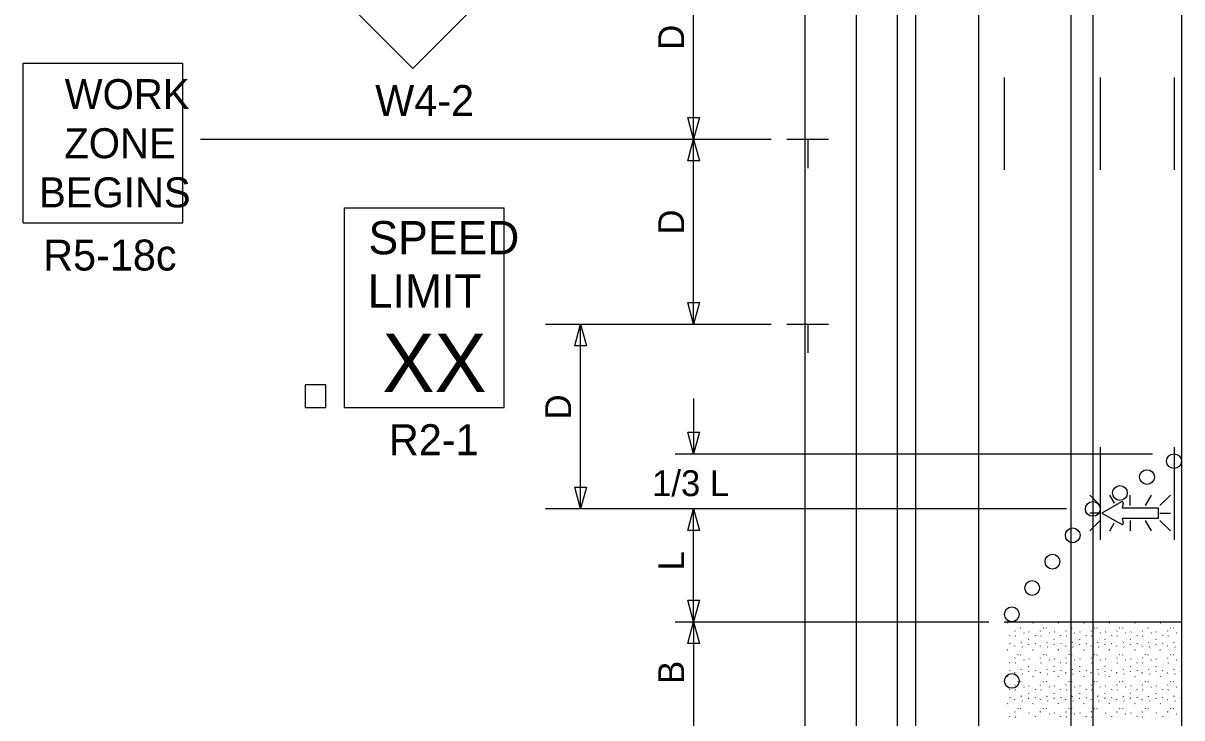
# Model space of a CAD drawing. Extents: x 16735 to 18475, y 6983 to 8262.
# Drawn here: x 16751.7 to 17065.2, y 7864.5 to 8052.4 of the extents above; entities that cross this region are included whole.
import ezdxf

# ---------------------------------------------------------------- set-up
doc = ezdxf.new("R2010")
doc.units = 0
for name, color, linetype in [('ALI_LEGAL_EX', 7, 'Continuous'), ('MT_SCRATCH_LEVEL_A', 7, 'Continuous'), ('PAVT_EDGE_EX', 7, 'Continuous'), ('TRAFFIC_SIGNS_PR', 7, 'Continuous'), ('TYPICAL_TEXT_DIMEN_PR', 7, 'Continuous')]:
    doc.layers.add(name, color=color, linetype=linetype)

msp = doc.modelspace()

# ---------------------------------------------------------------- linework, layer by layer
at = {"layer": 'ALI_LEGAL_EX'}
for points in [[(17017.08, 8037.7), (17017.08, 8012.7)], [(17043.08, 8037.7), (17043.08, 8012.7)], [(17063.08, 8037.7), (17063.08, 8012.7)], [(17043.08, 7937.7), (17043.08, 7912.7)], [(17063.08, 7937.7), (17063.08, 7912.7)]]:
    msp.add_lwpolyline(points, dxfattribs=at)
at = {"layer": 'MT_SCRATCH_LEVEL_A'}
for p, q in [((17017.08, 7890.49), (17065.16, 7890.49)), ((17018.01, 7890.13), (17018.06, 7890.25)), ((17024.9, 7890.13), (17024.95, 7890.25)), ((17031.78, 7890.13), (17031.83, 7890.25)), ((17038.67, 7890.13), (17038.72, 7890.25)), ((17045.56, 7890.13), (17045.61, 7890.25)), ((17052.45, 7890.13), (17052.5, 7890.25)), ((17059.33, 7890.13), (17059.39, 7890.25)), ((17018.58, 7886.81), (17018.63, 7886.73)), ((17020.03, 7887.93), (17020.08, 7888.05)), ((17020.11, 7886.67), (17020.16, 7886.59)), ((17020.79, 7888.89), (17020.84, 7888.82)), ((17021.53, 7888.87), (17021.58, 7888.79)), ((17022.4, 7887.49), (17022.45, 7887.41)), ((17023.85, 7887.64), (17023.9, 7887.75)), ((17025.47, 7886.81), (17025.52, 7886.73)), ((17026.92, 7887.93), (17026.97, 7888.05)), ((17027, 7886.67), (17027.05, 7886.59)), ((17027.68, 7888.89), (17027.73, 7888.82)), ((17028.42, 7888.87), (17028.47, 7888.79)), ((17029.28, 7887.49), (17029.34, 7887.41)), ((17030.74, 7887.64), (17030.79, 7887.75)), ((17032.35, 7886.81), (17032.4, 7886.73)), ((17033.8, 7887.93), (17033.85, 7888.05)), ((17033.88, 7886.67), (17033.94, 7886.59)), ((17034.57, 7888.89), (17034.62, 7888.82)), ((17035.3, 7888.87), (17035.36, 7888.79)), ((17036.17, 7887.49), (17036.22, 7887.41)), ((17037.62, 7887.64), (17037.67, 7887.75)), ((17039.24, 7886.81), (17039.29, 7886.73)), ((17040.69, 7887.93), (17040.74, 7888.05)), ((17040.77, 7886.67), (17040.82, 7886.59)), ((17041.46, 7888.89), (17041.51, 7888.82)), ((17042.19, 7888.87), (17042.24, 7888.79)), ((17043.06, 7887.49), (17043.11, 7887.41)), ((17044.51, 7887.64), (17044.56, 7887.75)), ((17046.13, 7886.81), (17046.18, 7886.73)), ((17047.58, 7887.93), (17047.63, 7888.05)), ((17047.66, 7886.67), (17047.71, 7886.59)), ((17048.34, 7888.89), (17048.39, 7888.82)), ((17049.08, 7888.87), (17049.13, 7888.79)), ((17049.95, 7887.49), (17050, 7887.41)), ((17051.4, 7887.64), (17051.45, 7887.75)), ((17053.02, 7886.81), (17053.07, 7886.73)), ((17054.47, 7887.93), (17054.52, 7888.05)), ((17054.55, 7886.67), (17054.6, 7886.59)), ((17055.23, 7888.89), (17055.28, 7888.82)), ((17055.97, 7888.87), (17056.02, 7888.79)), ((17056.84, 7887.49), (17056.89, 7887.41)), ((17058.28, 7887.64), (17058.34, 7887.75)), ((17059.9, 7886.81), (17059.96, 7886.73)), ((17061.35, 7887.93), (17061.4, 7888.05)), ((17061.43, 7886.67), (17061.49, 7886.59)), ((17062.12, 7888.89), (17062.17, 7888.82)), ((17062.85, 7888.87), (17062.91, 7888.79)), ((17063.72, 7887.49), (17063.78, 7887.41)), ((17018.63, 7884.6), (17018.68, 7884.52)), ((17019.91, 7884.02), (17019.92, 7883.91)), ((17021.75, 7884.88), (17021.8, 7885)), ((17021.94, 7883.68), (17021.99, 7883.6)), ((17023.67, 7885.75), (17023.73, 7885.67)), ((17023.72, 7884.35), (17023.77, 7884.46)), ((17025.51, 7884.6), (17025.57, 7884.52)), ((17026.8, 7884.02), (17026.81, 7883.91)), ((17028.64, 7884.88), (17028.69, 7885)), ((17028.83, 7883.68), (17028.88, 7883.6)), ((17030.56, 7885.75), (17030.61, 7885.67)), ((17030.6, 7884.35), (17030.66, 7884.46)), ((17032.4, 7884.6), (17032.45, 7884.52)), ((17033.68, 7884.02), (17033.7, 7883.91)), ((17035.53, 7884.88), (17035.58, 7885)), ((17035.71, 7883.68), (17035.76, 7883.6)), ((17037.45, 7885.75), (17037.5, 7885.67)), ((17037.49, 7884.35), (17037.54, 7884.46)), ((17039.29, 7884.6), (17039.34, 7884.52)), ((17040.57, 7884.02), (17040.58, 7883.91)), ((17042.41, 7884.88), (17042.46, 7885)), ((17042.6, 7883.68), (17042.65, 7883.6)), ((17044.34, 7885.75), (17044.39, 7885.67)), ((17044.38, 7884.35), (17044.43, 7884.46)), ((17046.18, 7884.6), (17046.23, 7884.52)), ((17047.46, 7884.02), (17047.47, 7883.91)), ((17049.3, 7884.88), (17049.35, 7885)), ((17049.49, 7883.68), (17049.54, 7883.6)), ((17051.22, 7885.75), (17051.28, 7885.67)), ((17051.27, 7884.35), (17051.32, 7884.46)), ((17053.06, 7884.6), (17053.12, 7884.52)), ((17054.35, 7884.02), (17054.36, 7883.91)), ((17056.19, 7884.88), (17056.24, 7885)), ((17056.38, 7883.68), (17056.43, 7883.6)), ((17058.11, 7885.75), (17058.16, 7885.67)), ((17058.15, 7884.35), (17058.21, 7884.46)), ((17059.95, 7884.6), (17060, 7884.52)), ((17061.23, 7884.02), (17061.25, 7883.91)), ((17063.08, 7884.88), (17063.13, 7885)), ((17063.26, 7883.68), (17063.31, 7883.6)), ((17065, 7885.75), (17065.05, 7885.67)), ((17065.04, 7884.35), (17065.1, 7884.46)), ((17018.01, 7882.85), (17018.06, 7882.96)), ((17020.03, 7880.65), (17020.08, 7880.77)), ((17020.79, 7881.61), (17020.84, 7881.53)), ((17021.53, 7881.58), (17021.58, 7881.5)), ((17023.85, 7880.35), (17023.9, 7880.47)), ((17024.9, 7882.85), (17024.95, 7882.96)), ((17026.92, 7880.65), (17026.97, 7880.77)), ((17027.68, 7881.61), (17027.73, 7881.53)), ((17028.42, 7881.58), (17028.47, 7881.5)), ((17030.74, 7880.35), (17030.79, 7880.47)), ((17031.78, 7882.85), (17031.83, 7882.96)), ((17033.8, 7880.65), (17033.85, 7880.77)), ((17034.57, 7881.61), (17034.62, 7881.53)), ((17035.3, 7881.58), (17035.36, 7881.5)), ((17037.62, 7880.35), (17037.67, 7880.47)), ((17038.67, 7882.85), (17038.72, 7882.96)), ((17040.69, 7880.65), (17040.74, 7880.77)), ((17041.46, 7881.61), (17041.51, 7881.53)), ((17042.19, 7881.58), (17042.24, 7881.5)), ((17044.51, 7880.35), (17044.56, 7880.47)), ((17045.56, 7882.85), (17045.61, 7882.96)), ((17047.58, 7880.65), (17047.63, 7880.77)), ((17048.34, 7881.61), (17048.39, 7881.53)), ((17049.08, 7881.58), (17049.13, 7881.5)), ((17051.4, 7880.35), (17051.45, 7880.47)), ((17052.45, 7882.85), (17052.5, 7882.96)), ((17054.47, 7880.65), (17054.52, 7880.77)), ((17055.23, 7881.61), (17055.28, 7881.53)), ((17055.97, 7881.58), (17056.02, 7881.5)), ((17058.28, 7880.35), (17058.34, 7880.47)), ((17059.33, 7882.85), (17059.39, 7882.96)), ((17061.35, 7880.65), (17061.4, 7880.77)), ((17062.12, 7881.61), (17062.17, 7881.53)), ((17062.85, 7881.58), (17062.91, 7881.5)), ((17018.58, 7879.52), (17018.63, 7879.45)), ((17018.63, 7877.31), (17018.68, 7877.24)), ((17020.11, 7879.38), (17020.16, 7879.31)), ((17021.75, 7877.59), (17021.8, 7877.71)), ((17022.4, 7880.2), (17022.45, 7880.12)), ((17023.67, 7878.46), (17023.73, 7878.39)), ((17025.47, 7879.52), (17025.52, 7879.45)), ((17025.51, 7877.31), (17025.57, 7877.24)), ((17027, 7879.38), (17027.05, 7879.31)), ((17028.64, 7877.59), (17028.69, 7877.71)), ((17029.28, 7880.2), (17029.34, 7880.12)), ((17030.56, 7878.46), (17030.61, 7878.39)), ((17032.35, 7879.52), (17032.4, 7879.45)), ((17032.4, 7877.31), (17032.45, 7877.24)), ((17033.88, 7879.38), (17033.94, 7879.31)), ((17035.53, 7877.59), (17035.58, 7877.71)), ((17036.17, 7880.2), (17036.22, 7880.12)), ((17037.45, 7878.46), (17037.5, 7878.39)), ((17039.24, 7879.52), (17039.29, 7879.45)), ((17039.29, 7877.31), (17039.34, 7877.24)), ((17040.77, 7879.38), (17040.82, 7879.31)), ((17042.41, 7877.59), (17042.46, 7877.71)), ((17043.06, 7880.2), (17043.11, 7880.12)), ((17044.34, 7878.46), (17044.39, 7878.39)), ((17046.13, 7879.52), (17046.18, 7879.45)), ((17046.18, 7877.31), (17046.23, 7877.24)), ((17047.66, 7879.38), (17047.71, 7879.31)), ((17049.3, 7877.59), (17049.35, 7877.71)), ((17049.95, 7880.2), (17050, 7880.12)), ((17051.22, 7878.46), (17051.28, 7878.39)), ((17053.02, 7879.52), (17053.07, 7879.45)), ((17053.06, 7877.31), (17053.12, 7877.24)), ((17054.55, 7879.38), (17054.6, 7879.31)), ((17056.19, 7877.59), (17056.24, 7877.71)), ((17056.84, 7880.2), (17056.89, 7880.12)), ((17058.11, 7878.46), (17058.16, 7878.39)), ((17059.9, 7879.52), (17059.96, 7879.45)), ((17059.95, 7877.31), (17060, 7877.24)), ((17061.43, 7879.38), (17061.49, 7879.31)), ((17063.08, 7877.59), (17063.13, 7877.71)), ((17063.72, 7880.2), (17063.78, 7880.12)), ((17065, 7878.46), (17065.05, 7878.39)), ((17018.01, 7875.56), (17018.06, 7875.68)), ((17019.91, 7876.74), (17019.92, 7876.62)), ((17020.79, 7874.32), (17020.84, 7874.25)), ((17021.53, 7874.3), (17021.58, 7874.22)), ((17021.94, 7876.4), (17021.99, 7876.32)), ((17023.72, 7877.06), (17023.77, 7877.18)), ((17024.9, 7875.56), (17024.95, 7875.68)), ((17026.8, 7876.74), (17026.81, 7876.62)), ((17027.68, 7874.32), (17027.73, 7874.25)), ((17028.42, 7874.3), (17028.47, 7874.22)), ((17028.83, 7876.4), (17028.88, 7876.32)), ((17030.6, 7877.06), (17030.66, 7877.18)), ((17031.78, 7875.56), (17031.83, 7875.68)), ((17033.68, 7876.74), (17033.7, 7876.62)), ((17034.57, 7874.32), (17034.62, 7874.25)), ((17035.3, 7874.3), (17035.36, 7874.22)), ((17035.71, 7876.4), (17035.76, 7876.32)), ((17037.49, 7877.06), (17037.54, 7877.18)), ((17038.67, 7875.56), (17038.72, 7875.68)), ((17040.57, 7876.74), (17040.58, 7876.62)), ((17041.46, 7874.32), (17041.51, 7874.25)), ((17042.19, 7874.3), (17042.24, 7874.22)), ((17042.6, 7876.4), (17042.65, 7876.32)), ((17044.38, 7877.06), (17044.43, 7877.18)), ((17045.56, 7875.56), (17045.61, 7875.68)), ((17047.46, 7876.74), (17047.47, 7876.62)), ((17048.34, 7874.32), (17048.39, 7874.25)), ((17049.08, 7874.3), (17049.13, 7874.22)), ((17049.49, 7876.4), (17049.54, 7876.32)), ((17051.27, 7877.06), (17051.32, 7877.18)), ((17052.45, 7875.56), (17052.5, 7875.68)), ((17054.35, 7876.74), (17054.36, 7876.62)), ((17055.23, 7874.32), (17055.28, 7874.25)), ((17055.97, 7874.3), (17056.02, 7874.22)), ((17056.38, 7876.4), (17056.43, 7876.32)), ((17058.15, 7877.06), (17058.21, 7877.18)), ((17059.33, 7875.56), (17059.39, 7875.68)), ((17061.23, 7876.74), (17061.25, 7876.62)), ((17062.12, 7874.32), (17062.17, 7874.25)), ((17062.85, 7874.3), (17062.91, 7874.22)), ((17063.26, 7876.4), (17063.31, 7876.32)), ((17065.04, 7877.06), (17065.1, 7877.18)), ((17018.58, 7872.24), (17018.63, 7872.16)), ((17020.03, 7873.37), (17020.08, 7873.48)), ((17020.11, 7872.1), (17020.16, 7872.02)), ((17022.4, 7872.92), (17022.45, 7872.84)), ((17023.67, 7871.18), (17023.73, 7871.1)), ((17023.85, 7873.07), (17023.9, 7873.18)), ((17025.47, 7872.24), (17025.52, 7872.16)), ((17026.92, 7873.37), (17026.97, 7873.48)), ((17027, 7872.1), (17027.05, 7872.02)), ((17029.28, 7872.92), (17029.34, 7872.84)), ((17030.56, 7871.18), (17030.61, 7871.1)), ((17030.74, 7873.07), (17030.79, 7873.18)), ((17032.35, 7872.24), (17032.4, 7872.16)), ((17033.8, 7873.37), (17033.85, 7873.48)), ((17033.88, 7872.1), (17033.94, 7872.02)), ((17036.17, 7872.92), (17036.22, 7872.84)), ((17037.45, 7871.18), (17037.5, 7871.1)), ((17037.62, 7873.07), (17037.67, 7873.18)), ((17039.24, 7872.24), (17039.29, 7872.16)), ((17040.69, 7873.37), (17040.74, 7873.48)), ((17040.77, 7872.1), (17040.82, 7872.02)), ((17043.06, 7872.92), (17043.11, 7872.84)), ((17044.34, 7871.18), (17044.39, 7871.1)), ((17044.51, 7873.07), (17044.56, 7873.18)), ((17046.13, 7872.24), (17046.18, 7872.16)), ((17047.58, 7873.37), (17047.63, 7873.48)), ((17047.66, 7872.1), (17047.71, 7872.02)), ((17049.95, 7872.92), (17050, 7872.84)), ((17051.22, 7871.18), (17051.28, 7871.1)), ((17051.4, 7873.07), (17051.45, 7873.18)), ((17053.02, 7872.24), (17053.07, 7872.16)), ((17054.47, 7873.37), (17054.52, 7873.48)), ((17054.55, 7872.1), (17054.6, 7872.02)), ((17056.84, 7872.92), (17056.89, 7872.84)), ((17058.11, 7871.18), (17058.16, 7871.1)), ((17058.28, 7873.07), (17058.34, 7873.18)), ((17059.9, 7872.24), (17059.96, 7872.16)), ((17061.35, 7873.37), (17061.4, 7873.48)), ((17061.43, 7872.1), (17061.49, 7872.02)), ((17063.72, 7872.92), (17063.78, 7872.84)), ((17065, 7871.18), (17065.05, 7871.1)), ((17018.01, 7868.28), (17018.06, 7868.39)), ((17018.63, 7870.03), (17018.68, 7869.95)), ((17019.91, 7869.45), (17019.92, 7869.34)), ((17021.75, 7870.31), (17021.8, 7870.43)), ((17021.94, 7869.11), (17021.99, 7869.03)), ((17023.72, 7869.78), (17023.77, 7869.9)), ((17024.9, 7868.28), (17024.95, 7868.39)), ((17025.51, 7870.03), (17025.57, 7869.95)), ((17026.8, 7869.45), (17026.81, 7869.34)), ((17028.64, 7870.31), (17028.69, 7870.43)), ((17028.83, 7869.11), (17028.88, 7869.03)), ((17030.6, 7869.78), (17030.66, 7869.9)), ((17031.78, 7868.28), (17031.83, 7868.39)), ((17032.4, 7870.03), (17032.45, 7869.95)), ((17033.68, 7869.45), (17033.7, 7869.34)), ((17035.53, 7870.31), (17035.58, 7870.43)), ((17035.71, 7869.11), (17035.76, 7869.03)), ((17037.49, 7869.78), (17037.54, 7869.9)), ((17038.67, 7868.28), (17038.72, 7868.39)), ((17039.29, 7870.03), (17039.34, 7869.95)), ((17040.57, 7869.45), (17040.58, 7869.34)), ((17042.41, 7870.31), (17042.46, 7870.43)), ((17042.6, 7869.11), (17042.65, 7869.03)), ((17044.38, 7869.78), (17044.43, 7869.9)), ((17045.56, 7868.28), (17045.61, 7868.39)), ((17046.18, 7870.03), (17046.23, 7869.95)), ((17047.46, 7869.45), (17047.47, 7869.34)), ((17049.3, 7870.31), (17049.35, 7870.43)), ((17049.49, 7869.11), (17049.54, 7869.03)), ((17051.27, 7869.78), (17051.32, 7869.9)), ((17052.45, 7868.28), (17052.5, 7868.39)), ((17053.06, 7870.03), (17053.12, 7869.95)), ((17054.35, 7869.45), (17054.36, 7869.34)), ((17056.19, 7870.31), (17056.24, 7870.43)), ((17056.38, 7869.11), (17056.43, 7869.03)), ((17058.15, 7869.78), (17058.21, 7869.9)), ((17059.33, 7868.28), (17059.39, 7868.39)), ((17059.95, 7870.03), (17060, 7869.95)), ((17061.23, 7869.45), (17061.25, 7869.34)), ((17063.08, 7870.31), (17063.13, 7870.43)), ((17063.26, 7869.11), (17063.31, 7869.03)), ((17065.04, 7869.78), (17065.1, 7869.9)), ((17018.58, 7864.95), (17018.63, 7864.88)), ((17020.03, 7866.08), (17020.08, 7866.2)), ((17020.11, 7864.81), (17020.16, 7864.74)), ((17020.79, 7867.04), (17020.84, 7866.96)), ((17021.53, 7867.01), (17021.58, 7866.93)), ((17022.4, 7865.63), (17022.45, 7865.55)), ((17023.85, 7865.78), (17023.9, 7865.9)), ((17025.47, 7864.95), (17025.52, 7864.88)), ((17026.92, 7866.08), (17026.97, 7866.2)), ((17027, 7864.81), (17027.05, 7864.74)), ((17027.68, 7867.04), (17027.73, 7866.96)), ((17028.42, 7867.01), (17028.47, 7866.93)), ((17029.28, 7865.63), (17029.34, 7865.55)), ((17030.74, 7865.78), (17030.79, 7865.9)), ((17032.35, 7864.95), (17032.4, 7864.88)), ((17033.8, 7866.08), (17033.85, 7866.2)), ((17033.88, 7864.81), (17033.94, 7864.74)), ((17034.57, 7867.04), (17034.62, 7866.96)), ((17035.3, 7867.01), (17035.36, 7866.93)), ((17036.17, 7865.63), (17036.22, 7865.55)), ((17037.62, 7865.78), (17037.67, 7865.9)), ((17039.24, 7864.95), (17039.29, 7864.88)), ((17040.69, 7866.08), (17040.74, 7866.2)), ((17040.77, 7864.81), (17040.82, 7864.74)), ((17041.46, 7867.04), (17041.51, 7866.96)), ((17042.19, 7867.01), (17042.24, 7866.93)), ((17043.06, 7865.63), (17043.11, 7865.55)), ((17044.51, 7865.78), (17044.56, 7865.9)), ((17046.13, 7864.95), (17046.18, 7864.88)), ((17047.58, 7866.08), (17047.63, 7866.2)), ((17047.66, 7864.81), (17047.71, 7864.74)), ((17048.34, 7867.04), (17048.39, 7866.96)), ((17049.08, 7867.01), (17049.13, 7866.93)), ((17049.95, 7865.63), (17050, 7865.55)), ((17051.4, 7865.78), (17051.45, 7865.9)), ((17053.02, 7864.95), (17053.07, 7864.88)), ((17054.47, 7866.08), (17054.52, 7866.2)), ((17054.55, 7864.81), (17054.6, 7864.74)), ((17055.23, 7867.04), (17055.28, 7866.96)), ((17055.97, 7867.01), (17056.02, 7866.93)), ((17056.84, 7865.63), (17056.89, 7865.55)), ((17058.28, 7865.78), (17058.34, 7865.9)), ((17059.9, 7864.95), (17059.96, 7864.88)), ((17061.35, 7866.08), (17061.4, 7866.2)), ((17061.43, 7864.81), (17061.49, 7864.74)), ((17062.12, 7867.04), (17062.17, 7866.96)), ((17062.85, 7867.01), (17062.91, 7866.93)), ((17063.72, 7865.63), (17063.78, 7865.55))]:
    msp.add_line(p, q, dxfattribs=at)
at = {"layer": 'PAVT_EDGE_EX'}
for p, q in [((16963.15, 8262.34), (16963.15, 7433.15)), ((16988.15, 8262.34), (16988.15, 7433.15)), ((17010.15, 8262.34), (17010.15, 7433.15)), ((17035.15, 8262.34), (17035.15, 7433.15)), ((16977.08, 8195.21), (16977.08, 7357.91)), ((16993.08, 8195.21), (16993.08, 7357.91)), ((17041.08, 8195.21), (17041.08, 7357.91)), ((17065.08, 8195.21), (17065.08, 7357.91))]:
    msp.add_line(p, q, dxfattribs=at)
at = {"layer": 'TRAFFIC_SIGNS_PR'}
for p, q in [((16826.58, 8070.72), (16857.12, 8040.17)), ((16857.12, 8040.17), (16887.67, 8070.72)), ((16751.7, 7998.38), (16751.7, 8041.58)), ((16751.7, 8041.58), (16794.9, 8041.58)), ((16794.9, 7998.38), (16794.9, 8041.58)), ((16838.64, 8002.43), (16881.84, 8002.43)), ((16838.64, 7948.43), (16838.64, 8002.43)), ((16881.84, 7948.43), (16881.84, 8002.43)), ((16751.7, 7998.38), (16794.9, 7998.38)), ((16838.64, 7948.43), (16881.84, 7948.43)), ((17040.26, 7924.75), (17043.08, 7921.93)), ((17046.98, 7922.57), (17045.72, 7924.75)), ((17051.17, 7921.93), (17051.17, 7924.75)), ((17055.3, 7921.93), (17056.93, 7924.75)), ((17059.25, 7921.93), (17062.07, 7924.76)), ((17043.08, 7919.9), (17040.26, 7919.9)), ((17059.25, 7919.9), (17062.07, 7919.9)), ((17040.26, 7915.05), (17043.08, 7917.87)), ((17045.7, 7915.05), (17046.9, 7917.14)), ((17051.17, 7917.87), (17051.17, 7915.05)), ((17056.96, 7915.05), (17055.33, 7917.87)), ((17059.25, 7917.87), (17062.07, 7915.05))]:
    msp.add_line(p, q, dxfattribs=at)
msp.add_lwpolyline([(16828.03, 7948.43), (16833.62, 7948.43), (16833.62, 7954.6), (16828.03, 7954.6)], close=True, dxfattribs=at)
for points in [[(17048.84, 7922.92), (17043.53, 7919.9), (17048.84, 7916.86)], [(17049.34, 7917.22), (17049.11, 7918.52), (17058.83, 7918.52), (17058.83, 7921.26), (17049.11, 7921.26), (17049.34, 7922.56)]]:
    msp.add_lwpolyline(points, dxfattribs=at)
for centre in [(17063.06, 7933.94), (17055.74, 7929.63), (17048.41, 7925.33), (17041.08, 7921.02), (17035.66, 7913.89), (17030.17, 7906.76), (17024.67, 7899.63), (17019.18, 7892.5), (17019.18, 7874.5)]:
    msp.add_circle(centre, 2, dxfattribs=at)
for centre, start, end in [((17049, 7922.62), 350.7308, 118.8916), ((17049, 7917.16), 241.4833, 9.9593)]:
    msp.add_arc(centre, 0.341, start, end, dxfattribs=at)
at = {"layer": 'TYPICAL_TEXT_DIMEN_PR'}
for p, q in [((16933.08, 8021.02), (16933.08, 8071.02)), ((16933.08, 8021.02), (16931.51, 8026.89)), ((16931.51, 8026.89), (16933.08, 8026.89)), ((16933.08, 8026.89), (16934.65, 8026.89)), ((16934.65, 8026.89), (16933.08, 8021.02)), ((16799.68, 8021.02), (16954.08, 8021.02)), ((16931.51, 8015.16), (16933.08, 8021.02)), ((16933.08, 8021.02), (16934.65, 8015.16)), ((16933.08, 7971.02), (16933.08, 8021.02)), ((16958.33, 8021.02), (16969.58, 8021.02)), ((16963.96, 8021.02), (16963.96, 8013.24)), ((16933.08, 8015.16), (16931.51, 8015.16)), ((16934.65, 8015.16), (16933.08, 8015.16)), ((16933.08, 7971.02), (16931.51, 7976.89)), ((16931.51, 7976.89), (16933.08, 7976.89)), ((16933.08, 7976.89), (16934.65, 7976.89)), ((16934.65, 7976.89), (16933.08, 7971.02)), ((16892.99, 7971.02), (16954.08, 7971.02)), ((16900.93, 7965.16), (16902.5, 7971.02)), ((16902.5, 7971.02), (16904.07, 7965.16)), ((16902.5, 7921.02), (16902.5, 7971.02)), ((16958.33, 7971.02), (16969.58, 7971.02)), ((16963.96, 7971.02), (16963.96, 7963.24)), ((16902.5, 7965.16), (16900.93, 7965.16)), ((16904.07, 7965.16), (16902.5, 7965.16)), ((16933.08, 7950.87), (16933.08, 7935.95)), ((16933.08, 7935.95), (16931.51, 7941.81)), ((16931.51, 7941.81), (16933.08, 7941.81)), ((16933.08, 7941.81), (16934.65, 7941.81)), ((16934.65, 7941.81), (16933.08, 7935.95)), ((16928.08, 7935.95), (17057.22, 7935.95)), ((16902.5, 7921.02), (16900.93, 7926.89)), ((16900.93, 7926.89), (16902.5, 7926.89)), ((16902.5, 7926.89), (16904.07, 7926.89)), ((16904.07, 7926.89), (16902.5, 7921.02)), ((17033.99, 7921.02), (16892.99, 7921.02)), ((17033.99, 7921.02), (16902.5, 7921.02)), ((16931.51, 7915.16), (16933.08, 7921.02)), ((16933.08, 7890.49), (16933.08, 7921.02)), ((16933.08, 7921.02), (16934.65, 7915.16)), ((16933.08, 7915.16), (16931.51, 7915.16)), ((16934.65, 7915.16), (16933.08, 7915.16)), ((17065.16, 7905.42), (17065.16, 7907.42)), ((16933.08, 7890.49), (16931.51, 7896.35)), ((16931.51, 7896.35), (16933.08, 7896.35)), ((16933.08, 7896.35), (16934.65, 7896.35)), ((16934.65, 7896.35), (16933.08, 7890.49)), ((16928.08, 7890.49), (17012.91, 7890.49)), ((16931.51, 7884.63), (16933.08, 7890.49)), ((16933.08, 7890.49), (16933.08, 7858.43)), ((16933.08, 7890.49), (16934.65, 7884.63)), ((16933.08, 7884.63), (16931.51, 7884.63)), ((16934.65, 7884.63), (16933.08, 7884.63))]:
    msp.add_line(p, q, dxfattribs=at)

# ---------------------------------------------------------------- texts
at = {"layer": 'TRAFFIC_SIGNS_PR'}
for s, height, p in [('WORK', 8.119, (16762.95, 8029.16)), ('W4-2', 8.37, (16846.95, 8027.31)), ('ZONE', 8.119, (16762.82, 8015.88)), ('BEGINS', 8.119, (16755.99, 8002.59)), ('SPEED', 9, (16845.13, 7989.9)), ('R5-18c', 8.37, (16757.12, 7985.51)), ('LIMIT', 9, (16844.94, 7975.5)), ('XX', 15.785, (16848.89, 7952.66)), ('R2-1', 8.37, (16850.65, 7935.56))]:
    msp.add_text(s, height=height, dxfattribs=at).set_placement(p)
at = {"layer": 'TYPICAL_TEXT_DIMEN_PR'}
for s, p in [('D', (16930.52, 8045.24)), ('D', (16930.52, 7995.24)), ('D', (16899.94, 7945.24)), ('L', (16930.52, 7904.36)), ('B', (16930.52, 7873.69))]:
    msp.add_text(s, height=7, rotation=90, dxfattribs=at).set_placement(p)
msp.add_text('1/3 L', height=7, dxfattribs=at).set_placement((16921.87, 7924.48))

doc.saveas('drawing.dxf')
